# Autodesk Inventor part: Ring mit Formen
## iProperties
Shininess: 64.0
Length Units: 11269
Angle Units: 11279
Time Units: 11290
Mass Units: 11283
Length Display Precision: 3
Angle Display Precision: 2
Compacted: True
Part Number: Ring mit Formen
Document SubType Name: Sheet Metal
Created: 2003-06
Material: Standard
Cost Center: 0.002 kg
Designer: juergen
Authority: 2102.1 mm^3
Density: 0.0
Volumn: 0.0
Area: 0.0
PropertySet Name: Model Information
Control State: 0
Master: False
Checked Out: False
SaveDate: 2003-06-22
SaveTime: 14:51
TotalMass: 0.002 kg
TotalVolume: 2102.1 mm^3
SM_Thickness: 0.5 mm
SM_Style: Standard
Author: juergen
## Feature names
1. Extrusion1
2. Platte1
3. Biegung1
4. Ausklinkung1
5. Ausklinkung2
